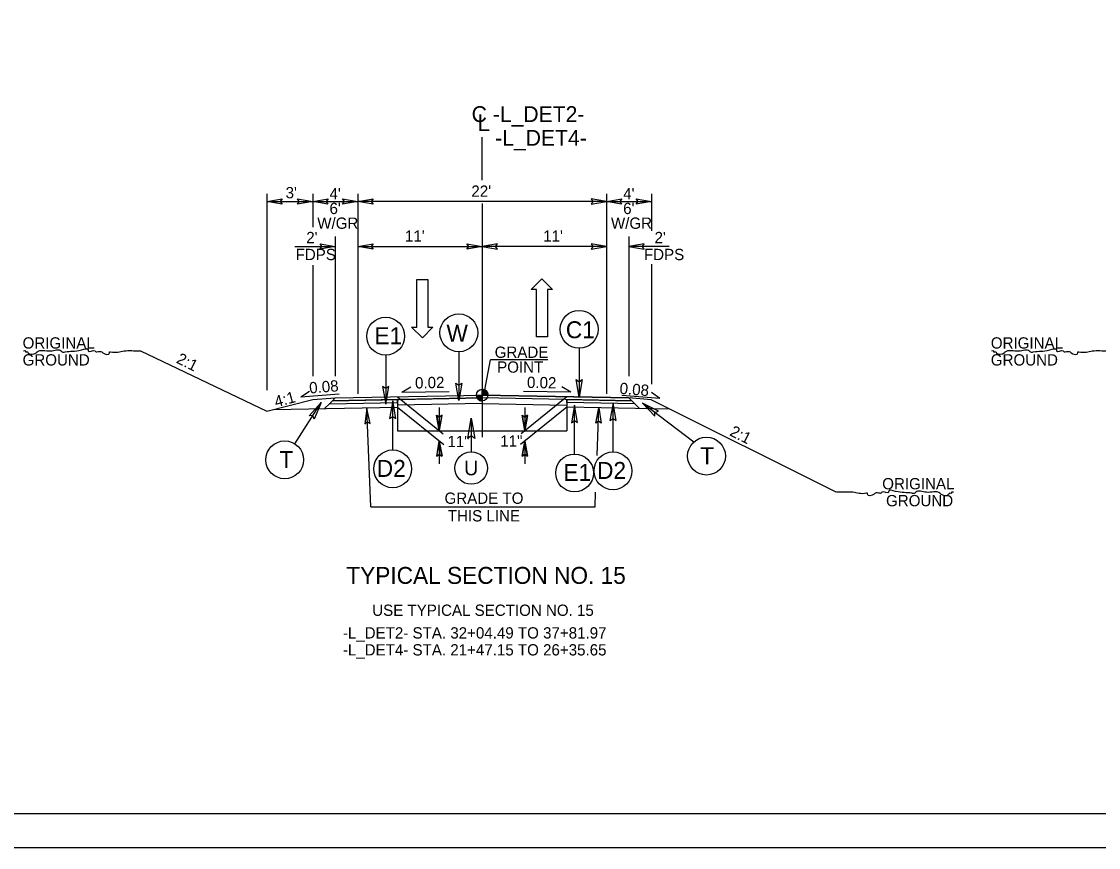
# Model space of a CAD drawing. Extents: x 18938 to 19565, y 6931 to 7973.
# Drawn here: x 19203.1 to 19298.4, y 7077.8 to 7150.9 of the extents above; entities that cross this region are included whole.
import ezdxf

# ---------------------------------------------------------------- set-up
doc = ezdxf.new("R2010")
doc.units = 0
for name, color, linetype in [('Old_Level_11', 7, 'Continuous'), ('Old_Level_2', 7, 'Continuous'), ('Prop Dimension', 7, 'Continuous'), ('Prop Pavement Schedule Description CELL', 7, 'Continuous'), ('Prop Shade Medium', 7, 'Continuous'), ('Prop Terminator CELL', 7, 'Continuous'), ('Sheet Block Title CELL', 7, 'Continuous'), ('Sheet Data Field CELL', 7, 'Continuous'), ('Sheet Plot Border Outside CELL', 7, 'Continuous'), ('Sheet Typical CELL', 7, 'Continuous'), ('Typical Curb CELL', 7, 'Continuous'), ('Typical Detail Wedge1 CELL', 7, 'Continuous'), ('Typical Detail Wedge2 CELL', 7, 'Continuous'), ('Typical Detail Wedge3 CELL', 7, 'Continuous'), ('Typical Hinge Slope Arterial CELL', 7, 'Continuous'), ('Typical ID Circle CELL', 7, 'Continuous'), ('Typical Pavement Slope Information CELL', 7, 'Continuous'), ('Typical Shoulder Slope Information CELL', 7, 'Continuous'), ('Typical Terminator CELL', 7, 'Continuous'), ('Typical Text General CELL', 7, 'Continuous'), ('Typical Text Grade Point CELL', 7, 'Continuous'), ('Typical Text ID Circle CELL', 7, 'Continuous'), ('Typical Text Label CELL', 7, 'Continuous')]:
    doc.layers.add(name, color=color, linetype=linetype)

msp = doc.modelspace()

# ---------------------------------------------------------------- linework, layer by layer
at = {"layer": 'Prop Dimension'}
msp.add_lwpolyline([(19155.167, 7077.771), (19382.434, 7077.771), (19382.434, 7224.204), (19155.167, 7224.204)], close=True, dxfattribs=at)
at = {"layer": 'Prop Pavement Schedule Description CELL'}
for p, q in [((19228.852, 7117.446), (19230.852, 7117.569)), ((19230.596, 7117.314), (19243.852, 7117.579)), ((19230.596, 7117.314), (19230.852, 7117.569)), ((19230.852, 7117.569), (19243.852, 7117.829)), ((19256.852, 7117.569), (19243.851, 7117.829)), ((19257.107, 7117.314), (19243.851, 7117.579)), ((19258.814, 7117.412), (19256.852, 7117.569)), ((19257.107, 7117.314), (19256.852, 7117.569)), ((19275.206, 7109.216), (19258.814, 7117.412)), ((19225.377, 7116.543), (19236.352, 7116.763)), ((19229.908, 7116.634), (19230.341, 7117.058)), ((19260.477, 7116.58), (19251.352, 7116.763)), ((19257.795, 7116.634), (19257.362, 7117.058))]:
    msp.add_line(p, q, dxfattribs=at)
at = {"layer": 'Prop Shade Medium'}
for p, q in [((19213.61, 7121.735), (19224.785, 7116.389)), ((19224.785, 7116.389), (19228.852, 7117.446))]:
    msp.add_line(p, q, dxfattribs=at)
at = {"layer": 'Sheet Block Title CELL'}
for p, q in [((19236.352, 7117.429), (19230.596, 7117.314)), ((19236.352, 7117.429), (19230.596, 7117.314)), ((19236.352, 7117.179), (19236.352, 7117.429)), ((19236.352, 7117.179), (19236.352, 7117.429)), ((19251.352, 7117.429), (19257.107, 7117.314)), ((19251.352, 7117.179), (19251.352, 7117.429)), ((19230.596, 7117.314), (19230.341, 7117.058)), ((19230.596, 7117.314), (19230.341, 7117.058)), ((19230.341, 7117.058), (19236.352, 7117.179)), ((19230.341, 7117.058), (19236.352, 7117.179)), ((19257.362, 7117.058), (19251.352, 7117.179)), ((19257.107, 7117.314), (19257.362, 7117.058))]:
    msp.add_line(p, q, dxfattribs=at)
at = {"layer": 'Sheet Data Field CELL'}
for points in [[(19226.135, 7134.723), (19224.785, 7134.955), (19226.142, 7135.195), (19225.97, 7134.955)], [(19227.502, 7135.188), (19228.852, 7134.955), (19227.494, 7134.715), (19227.667, 7134.955)], [(19230.202, 7134.723), (19228.852, 7134.955), (19230.209, 7135.195), (19230.037, 7134.955)], [(19231.502, 7135.188), (19232.852, 7134.955), (19231.494, 7134.715), (19231.667, 7134.955)], [(19234.202, 7134.723), (19232.852, 7134.955), (19234.209, 7135.195), (19234.037, 7134.955)], [(19253.502, 7134.723), (19254.852, 7134.955), (19253.494, 7135.195), (19253.667, 7134.955)], [(19256.202, 7134.723), (19254.852, 7134.955), (19256.209, 7135.195), (19256.037, 7134.955)], [(19257.502, 7135.188), (19258.852, 7134.955), (19257.494, 7134.715), (19257.667, 7134.955)], [(19229.502, 7131.209), (19230.852, 7130.977), (19229.494, 7130.737), (19229.667, 7130.977)], [(19234.202, 7130.744), (19232.852, 7130.977), (19234.209, 7131.217), (19234.037, 7130.977)], [(19242.502, 7131.209), (19243.852, 7130.977), (19242.494, 7130.737), (19242.667, 7130.977)], [(19245.202, 7131.209), (19243.852, 7130.977), (19245.209, 7130.737), (19245.037, 7130.977)], [(19253.502, 7130.744), (19254.852, 7130.977), (19253.494, 7131.217), (19253.667, 7130.977)], [(19258.202, 7131.209), (19256.852, 7130.977), (19258.209, 7130.737), (19258.037, 7130.977)], [(19233.927, 7115.304), (19233.649, 7116.645), (19233.455, 7115.28), (19233.689, 7115.461)], [(19253.918, 7115.351), (19254.196, 7116.692), (19254.39, 7115.327), (19254.156, 7115.508)], [(19240.293, 7116.024), (19240.061, 7114.674), (19239.821, 7116.032), (19240.061, 7115.859)], [(19239.828, 7116.024), (19240.061, 7114.674), (19240.301, 7116.032), (19240.061, 7115.859)], [(19242.581, 7113.992), (19242.891, 7115.792), (19243.211, 7113.982), (19242.891, 7114.212)], [(19247.875, 7116.024), (19247.642, 7114.674), (19247.402, 7116.032), (19247.642, 7115.859)], [(19247.41, 7116.024), (19247.642, 7114.674), (19247.882, 7116.032), (19247.642, 7115.859)], [(19240.293, 7112.408), (19240.06, 7113.758), (19239.82, 7112.401), (19240.06, 7112.573)], [(19239.829, 7112.408), (19240.061, 7113.758), (19240.301, 7112.401), (19240.061, 7112.573)], [(19247.874, 7112.408), (19247.642, 7113.758), (19247.402, 7112.401), (19247.642, 7112.573)], [(19247.41, 7112.408), (19247.643, 7113.758), (19247.883, 7112.401), (19247.643, 7112.573)]]:
    msp.add_lwpolyline(points, close=True, dxfattribs=at)
at = {"layer": 'Sheet Typical CELL'}
for p, q in [((19224.785, 7135.647), (19224.785, 7118.256)), ((19228.852, 7135.647), (19228.852, 7132.689)), ((19232.852, 7135.647), (19232.852, 7117.941)), ((19254.852, 7135.647), (19254.852, 7117.941)), ((19258.852, 7135.647), (19258.852, 7132.376)), ((19224.785, 7134.955), (19228.852, 7134.955)), ((19228.852, 7134.955), (19232.852, 7134.955)), ((19254.852, 7134.955), (19232.852, 7134.955)), ((19254.852, 7134.955), (19258.852, 7134.955)), ((19230.852, 7131.879), (19230.852, 7119.499)), ((19256.852, 7131.879), (19256.852, 7119.499)), ((19227.28, 7130.977), (19230.852, 7130.977)), ((19232.852, 7130.977), (19243.852, 7130.977)), ((19254.852, 7130.977), (19243.852, 7130.977)), ((19260.423, 7130.977), (19256.852, 7130.977)), ((19228.852, 7129.334), (19228.852, 7119.499)), ((19258.852, 7129.406), (19258.852, 7118.796)), ((19236.352, 7117.679), (19240.407, 7114.394)), ((19251.352, 7117.679), (19247.296, 7114.394)), ((19233.99, 7107.916), (19233.649, 7116.645)), ((19236.352, 7116.763), (19240.456, 7113.438)), ((19240.061, 7116.718), (19240.061, 7114.674)), ((19240.061, 7116.718), (19240.061, 7114.674)), ((19251.352, 7116.763), (19247.247, 7113.438)), ((19247.642, 7116.718), (19247.642, 7114.674)), ((19247.642, 7116.718), (19247.642, 7114.674)), ((19254.028, 7112.462), (19254.194, 7116.706)), ((19240.06, 7113.758), (19240.06, 7111.735)), ((19240.061, 7113.758), (19240.061, 7111.735)), ((19247.642, 7113.758), (19247.642, 7111.735)), ((19247.643, 7113.758), (19247.643, 7111.735)), ((19253.851, 7107.916), (19253.902, 7109.233)), ((19233.99, 7107.916), (19253.851, 7107.916))]:
    msp.add_line(p, q, dxfattribs=at)
at = {"layer": 'Typical Curb CELL'}
for points in [[(19203.245, 7121.735), (19203.417, 7121.735), (19203.417, 7121.649), (19203.588, 7121.649), (19203.674, 7121.564), (19204.359, 7121.564), (19204.444, 7121.649), (19205.644, 7121.735), (19206.586, 7121.735), (19206.672, 7121.649), (19206.929, 7121.649), (19208.385, 7121.821), (19208.984, 7121.821), (19208.984, 7121.735), (19209.584, 7121.735), (19209.669, 7121.649), (19209.755, 7121.649), (19210.183, 7121.649), (19210.269, 7121.564), (19210.869, 7121.564), (19210.869, 7121.649), (19210.954, 7121.649), (19212.153, 7121.735), (19213.524, 7121.735), (19213.61, 7121.735)], [(19288.966, 7121.735), (19289.137, 7121.735), (19289.137, 7121.649), (19289.308, 7121.649), (19289.394, 7121.564), (19290.079, 7121.564), (19290.165, 7121.649), (19291.364, 7121.735), (19292.306, 7121.735), (19292.392, 7121.649), (19292.649, 7121.649), (19294.105, 7121.821), (19294.705, 7121.821), (19294.705, 7121.735), (19295.304, 7121.735), (19295.39, 7121.649), (19295.475, 7121.649), (19295.904, 7121.649), (19295.989, 7121.564), (19296.589, 7121.564), (19296.589, 7121.649), (19296.674, 7121.649), (19297.874, 7121.735), (19299.244, 7121.735), (19299.33, 7121.735)], [(19285.583, 7109.215), (19285.412, 7109.215), (19285.412, 7109.129), (19285.241, 7109.129), (19285.155, 7109.043), (19284.47, 7109.043), (19284.384, 7109.129), (19283.185, 7109.215), (19282.243, 7109.215), (19282.157, 7109.129), (19281.9, 7109.129), (19280.444, 7109.301), (19279.844, 7109.301), (19279.844, 7109.215), (19279.245, 7109.215), (19279.159, 7109.129), (19279.073, 7109.129), (19278.645, 7109.129), (19278.559, 7109.043), (19277.96, 7109.043), (19277.96, 7109.129), (19277.874, 7109.129), (19276.675, 7109.215), (19275.305, 7109.215), (19275.219, 7109.215)]]:
    msp.add_spline(points, degree=3, dxfattribs=at)
at = {"layer": 'Typical Detail Wedge1 CELL'}
for p, q in [((19243.34, 7117.829), (19243.852, 7117.829)), ((19243.851, 7117.316), (19243.852, 7117.829)), ((19243.852, 7117.829), (19243.851, 7117.316)), ((19243.852, 7117.829), (19243.852, 7118.341)), ((19244.364, 7117.829), (19243.852, 7117.829))]:
    msp.add_line(p, q, dxfattribs=at)
for points in [[(19243.342, 7117.829), (19243.342, 7117.773)], [(19243.353, 7117.829), (19243.353, 7117.713)], [(19243.363, 7117.829), (19243.363, 7117.675)], [(19243.373, 7117.829), (19243.373, 7117.646)], [(19243.384, 7117.829), (19243.384, 7117.621)], [(19243.394, 7117.829), (19243.394, 7117.599)], [(19243.404, 7117.829), (19243.404, 7117.58)], [(19243.414, 7117.829), (19243.414, 7117.563)], [(19243.425, 7117.829), (19243.425, 7117.546)], [(19243.435, 7117.829), (19243.435, 7117.531)], [(19243.445, 7117.829), (19243.445, 7117.518)], [(19243.455, 7117.829), (19243.455, 7117.505)], [(19243.465, 7117.829), (19243.465, 7117.492)], [(19243.476, 7117.829), (19243.476, 7117.481)], [(19243.486, 7117.829), (19243.486, 7117.47)], [(19243.496, 7117.829), (19243.496, 7117.46)], [(19243.506, 7117.829), (19243.506, 7117.451)], [(19243.517, 7117.829), (19243.516, 7117.442)], [(19243.527, 7117.829), (19243.527, 7117.433)], [(19243.537, 7117.829), (19243.537, 7117.424)], [(19243.547, 7117.829), (19243.547, 7117.417)], [(19243.558, 7117.829), (19243.558, 7117.409)], [(19243.568, 7117.829), (19243.568, 7117.402)], [(19243.578, 7117.829), (19243.578, 7117.396)], [(19243.589, 7117.829), (19243.588, 7117.389)], [(19243.599, 7117.829), (19243.599, 7117.383)], [(19243.609, 7117.829), (19243.609, 7117.378)], [(19243.619, 7117.829), (19243.619, 7117.372)], [(19243.629, 7117.829), (19243.629, 7117.367)], [(19243.64, 7117.829), (19243.639, 7117.363)], [(19243.65, 7117.829), (19243.65, 7117.358)], [(19243.66, 7117.829), (19243.66, 7117.354)], [(19243.67, 7117.829), (19243.67, 7117.35)], [(19243.681, 7117.829), (19243.681, 7117.346)], [(19243.691, 7117.829), (19243.691, 7117.342)], [(19243.701, 7117.829), (19243.701, 7117.339)], [(19243.711, 7117.829), (19243.711, 7117.336)], [(19243.721, 7117.829), (19243.721, 7117.333)], [(19243.732, 7117.829), (19243.732, 7117.331)], [(19243.742, 7117.829), (19243.742, 7117.328)], [(19243.752, 7117.829), (19243.752, 7117.326)], [(19243.762, 7117.829), (19243.762, 7117.325)], [(19243.773, 7117.829), (19243.773, 7117.323)], [(19243.783, 7117.829), (19243.783, 7117.321)], [(19243.793, 7117.829), (19243.793, 7117.32)], [(19243.804, 7117.829), (19243.803, 7117.319)], [(19243.814, 7117.829), (19243.814, 7117.318)], [(19243.824, 7117.829), (19243.824, 7117.318)], [(19243.834, 7117.829), (19243.834, 7117.317)], [(19243.844, 7117.829), (19243.844, 7117.316), (19243.844, 7117.316)], [(19243.857, 7118.341), (19243.857, 7118.341), (19243.857, 7117.829)], [(19243.867, 7118.34), (19243.867, 7117.829)], [(19243.877, 7118.34), (19243.877, 7117.829)], [(19243.888, 7118.339), (19243.887, 7117.829)], [(19243.898, 7118.338), (19243.898, 7117.829)], [(19243.908, 7118.338), (19243.908, 7117.829)], [(19243.918, 7118.336), (19243.918, 7117.829)], [(19243.928, 7118.335), (19243.928, 7117.829)], [(19243.939, 7118.333), (19243.938, 7117.829)], [(19243.949, 7118.331), (19243.949, 7117.829)], [(19243.959, 7118.329), (19243.959, 7117.829)], [(19243.969, 7118.327), (19243.969, 7117.829)], [(19243.98, 7118.324), (19243.979, 7117.829)], [(19243.99, 7118.321), (19243.99, 7117.829)], [(19244, 7118.319), (19244, 7117.829)], [(19244.01, 7118.316), (19244.01, 7117.829)], [(19244.021, 7118.312), (19244.02, 7117.829)], [(19244.031, 7118.308), (19244.031, 7117.829)], [(19244.041, 7118.304), (19244.041, 7117.829)], [(19244.051, 7118.3), (19244.051, 7117.829)], [(19244.062, 7118.295), (19244.062, 7117.829)], [(19244.072, 7118.291), (19244.072, 7117.829)], [(19244.082, 7118.286), (19244.082, 7117.829)], [(19244.092, 7118.28), (19244.092, 7117.829)], [(19244.103, 7118.275), (19244.102, 7117.829)], [(19244.113, 7118.269), (19244.113, 7117.829)], [(19244.123, 7118.263), (19244.123, 7117.829)], [(19244.133, 7118.256), (19244.133, 7117.829)], [(19244.143, 7118.249), (19244.143, 7117.829)], [(19244.154, 7118.242), (19244.154, 7117.829)], [(19244.164, 7118.234), (19244.164, 7117.829)], [(19244.174, 7118.226), (19244.174, 7117.829)], [(19244.184, 7118.218), (19244.184, 7117.829)], [(19244.195, 7118.208), (19244.194, 7117.828)], [(19244.205, 7118.199), (19244.205, 7117.829)], [(19244.215, 7118.189), (19244.215, 7117.828)], [(19244.225, 7118.179), (19244.225, 7117.828)], [(19244.236, 7118.167), (19244.236, 7117.829)], [(19244.246, 7118.155), (19244.246, 7117.828)], [(19244.256, 7118.142), (19244.256, 7117.828)], [(19244.266, 7118.129), (19244.266, 7117.829)], [(19244.277, 7118.114), (19244.277, 7117.828)], [(19244.287, 7118.098), (19244.287, 7117.828)], [(19244.297, 7118.081), (19244.297, 7117.829)], [(19244.307, 7118.062), (19244.307, 7117.828)], [(19244.318, 7118.041), (19244.317, 7117.828)], [(19244.328, 7118.017), (19244.328, 7117.829)], [(19244.338, 7117.988), (19244.338, 7117.828)], [(19244.348, 7117.953), (19244.348, 7117.828)], [(19244.358, 7117.901), (19244.358, 7117.829)]]:
    msp.add_lwpolyline(points, dxfattribs=at)
msp.add_circle((19243.852, 7117.829), 0.512, dxfattribs=at)
for start, end in [(179.99048, 269.99048), (359.99048, 89.99048)]:
    msp.add_arc((19243.852, 7117.829), 0.512, start, end, dxfattribs=at)
at = {"layer": 'Typical Detail Wedge3 CELL'}
for p, q in [((19238.059, 7123.847), (19238.059, 7128.047)), ((19238.059, 7128.047), (19239.049, 7128.047)), ((19239.049, 7128.047), (19239.049, 7123.847)), ((19248.204, 7127.176), (19249.134, 7128.121)), ((19249.134, 7128.121), (19250.094, 7127.176)), ((19248.654, 7127.176), (19248.204, 7127.176)), ((19248.654, 7122.976), (19248.654, 7127.176)), ((19250.094, 7127.176), (19249.644, 7127.176)), ((19249.644, 7127.176), (19249.644, 7122.976)), ((19238.569, 7122.902), (19237.609, 7123.847)), ((19237.609, 7123.847), (19238.059, 7123.847)), ((19239.499, 7123.847), (19238.569, 7122.902)), ((19239.049, 7123.847), (19239.499, 7123.847)), ((19249.644, 7122.976), (19248.654, 7122.976))]:
    msp.add_line(p, q, dxfattribs=at)
at = {"layer": 'Typical Hinge Slope Arterial CELL'}
for p, q in [((19230.596, 7117.314), (19230.852, 7117.569)), ((19230.852, 7117.569), (19243.852, 7117.829)), ((19243.852, 7117.579), (19230.852, 7117.319)), ((19243.852, 7117.829), (19256.852, 7117.569)), ((19257.107, 7117.314), (19243.852, 7117.579)), ((19256.852, 7117.569), (19257.107, 7117.314)), ((19230.852, 7117.319), (19230.596, 7117.314)), ((19230.852, 7117.319), (19230.852, 7117.319))]:
    msp.add_line(p, q, dxfattribs=at)
at = {"layer": 'Typical ID Circle CELL'}
for p, q in [((19236.352, 7117.429), (19236.352, 7114.647)), ((19251.352, 7117.429), (19251.352, 7114.647)), ((19243.852, 7117.068), (19236.352, 7116.918)), ((19243.852, 7117.068), (19251.352, 7116.918)), ((19236.352, 7114.647), (19251.352, 7114.647))]:
    msp.add_line(p, q, dxfattribs=at)
at = {"layer": 'Typical Pavement Slope Information CELL'}
msp.add_lwpolyline([(19380.142, 7221.197), (19177.642, 7221.197), (19177.642, 7080.781), (19380.142, 7080.781)], close=True, dxfattribs=at)
at = {"layer": 'Typical Terminator CELL'}
for p, q in [((19235.314, 7121.364), (19235.314, 7117.033)), ((19241.793, 7121.663), (19241.793, 7117.332)), ((19252.44, 7121.972), (19252.44, 7117.64)), ((19227.274, 7113.502), (19229.601, 7117.155)), ((19235.936, 7112.971), (19235.936, 7117.302)), ((19252.039, 7112.605), (19252.039, 7116.936)), ((19255.44, 7112.791), (19255.44, 7117.122)), ((19262.589, 7113.667), (19258.062, 7117.12)), ((19242.891, 7115.792), (19242.891, 7112.809))]:
    msp.add_line(p, q, dxfattribs=at)
for centre, radius in [((19252.44, 7123.647), 1.676), ((19235.314, 7123.04), 1.676), ((19241.793, 7123.339), 1.676), ((19226.374, 7112.089), 1.676), ((19263.713, 7112.424), 1.676), ((19235.936, 7111.295), 1.676), ((19242.891, 7111.366), 1.443), ((19255.44, 7111.115), 1.676), ((19252.039, 7110.929), 1.676)]:
    msp.add_circle(centre, radius, dxfattribs=at)
at = {"layer": 'Typical Text General CELL'}
for points in [[(19235.046, 7118.584), (19235.314, 7117.033), (19235.589, 7118.593), (19235.314, 7118.395)], [(19242.061, 7118.884), (19241.793, 7117.332), (19241.517, 7118.893), (19241.793, 7118.694)], [(19252.707, 7119.192), (19252.44, 7117.64), (19252.164, 7119.201), (19252.44, 7119.003)], [(19228.542, 7115.99), (19229.601, 7117.155), (19228.995, 7115.691), (19228.869, 7116.006)], [(19236.203, 7115.75), (19235.936, 7117.302), (19235.66, 7115.742), (19235.936, 7115.94)], [(19252.306, 7115.384), (19252.039, 7116.936), (19251.763, 7115.375), (19252.039, 7115.574)], [(19255.707, 7115.57), (19255.44, 7117.122), (19255.164, 7115.562), (19255.44, 7115.76)], [(19259.458, 7116.392), (19258.062, 7117.12), (19259.135, 7115.955), (19259.145, 7116.294)]]:
    msp.add_lwpolyline(points, close=True, dxfattribs=at)
at = {"layer": 'Typical Text Grade Point CELL'}
for p, q in [((19236.756, 7118.069), (19237.539, 7118.542)), ((19251.7, 7118.069), (19250.917, 7118.542)), ((19227.802, 7117.657), (19228.555, 7118.176)), ((19227.802, 7117.657), (19231.188, 7117.928)), ((19236.756, 7118.069), (19240.945, 7118.153)), ((19251.7, 7118.069), (19247.511, 7118.153)), ((19259.598, 7117.523), (19256.212, 7117.794)), ((19259.598, 7117.523), (19258.844, 7118.042))]:
    msp.add_line(p, q, dxfattribs=at)
at = {"layer": 'Typical Text ID Circle CELL'}
for p, q in [((19243.837, 7140.658), (19243.837, 7136.863)), ((19243.852, 7134.773), (19243.852, 7114.092)), ((19244.102, 7118.282), (19244.597, 7120.95)), ((19249.674, 7120.949), (19244.597, 7120.95))]:
    msp.add_line(p, q, dxfattribs=at)

# ---------------------------------------------------------------- texts
at = {"layer": 'Old_Level_11'}
for s, height, p in [('TYPICAL SECTION NO. 15', 1.5, (19231.828, 7101.109)), ('USE TYPICAL SECTION NO. 15', 1, (19234.123, 7098.275))]:
    msp.add_text(s, height=height, dxfattribs=at).set_placement(p)
at = {"layer": 'Old_Level_2'}
for s, p in [('ORIGINAL', (19203.169, 7121.941)), ('ORIGINAL', (19288.889, 7121.941)), ('GROUND', (19203.169, 7120.441)), ('GROUND', (19288.889, 7120.441))]:
    msp.add_text(s, height=1, rotation=360, dxfattribs=at).set_placement(p)
for s, p in [('ORIGINAL', (19279.275, 7109.478)), ('GROUND', (19279.612, 7107.978))]:
    msp.add_text(s, height=1, dxfattribs=at).set_placement(p)
at = {"layer": 'Prop Terminator CELL'}
for s, height, p in [('C1', 1.5, (19251.266, 7122.859)), ('W', 1.5, (19240.699, 7122.551)), ('T', 1.5, (19263.168, 7111.704)), ('U', 1.291, (19242.259, 7110.721))]:
    msp.add_text(s, height=height, dxfattribs=at).set_placement(p)
for s, p in [('E1', (19234.322, 7122.328)), ('T', (19225.905, 7111.369)), ('D2', (19234.526, 7110.583)), ('E1', (19251.047, 7110.217)), ('D2', (19254.03, 7110.403))]:
    msp.add_text(s, height=1.5, rotation=360, dxfattribs=at).set_placement(p)
at = {"layer": 'Sheet Plot Border Outside CELL'}
for s, p in [('GRADE', (19244.962, 7121.118)), ('POINT', (19245.181, 7119.807))]:
    msp.add_text(s, height=1, rotation=0.00004, dxfattribs=at).set_placement(p)
at = {"layer": 'Typical Detail Wedge2 CELL'}
for s, p in [("3'", (19226.455, 7135.245)), ("4'", (19230.342, 7135.156)), ("22'", (19242.902, 7135.381)), ("4'", (19256.342, 7135.156)), ("6' ", (19230.342, 7133.851)), ("6' ", (19256.342, 7133.851)), ('W/GR', (19229.257, 7132.546)), ('W/GR', (19255.257, 7132.546)), ("2'", (19228.28, 7131.273)), ("11'", (19237.022, 7131.402)), ("11'", (19249.261, 7131.402)), ("2'", (19259.119, 7131.273)), ('FDPS', (19227.34, 7129.773)), ('FDPS', (19258.179, 7129.773)), ('11"', (19240.781, 7113.213)), ('11"', (19245.461, 7113.262)), ('GRADE TO', (19240.525, 7108.194)), ('THIS LINE', (19240.816, 7106.638)), ('-L_DET2- STA. 32+04.49 TO 37+81.97', (19231.522, 7096.269)), ('-L_DET4- STA. 21+47.15 TO 26+35.65 ', (19231.522, 7094.769))]:
    msp.add_text(s, height=1, dxfattribs=at).set_placement(p)
at = {"layer": 'Typical Shoulder Slope Information CELL'}
for s, rotation, p in [('2:1', 333.43491, (19216.707, 7120.718)), ('4:1', 15.1346, (19225.612, 7116.729)), (' 2:1', 333.43491, (19265.364, 7114.449))]:
    msp.add_text(s, height=1, rotation=rotation, dxfattribs=at).set_placement(p)
at = {"layer": 'Typical Text Grade Point CELL'}
for s, rotation, p in [('0.02', 1.14574, (19237.923, 7118.404)), ('0.02', 358.85426, (19247.815, 7118.458)), ('0.08', 4.5738, (19228.583, 7117.958)), ('0.08', 355.4262, (19255.994, 7117.936))]:
    msp.add_text(s, height=1, rotation=rotation, dxfattribs=at).set_placement(p)
at = {"layer": 'Typical Text Label CELL'}
for s, height, p in [('C -L_DET2-', 1.4, (19242.923, 7142.001)), ('L', 1.5, (19243.439, 7141.194)), ('    -L_DET4-', 1.4, (19242.923, 7139.901))]:
    msp.add_text(s, height=height, dxfattribs=at).set_placement(p)

doc.saveas('drawing.dxf')
